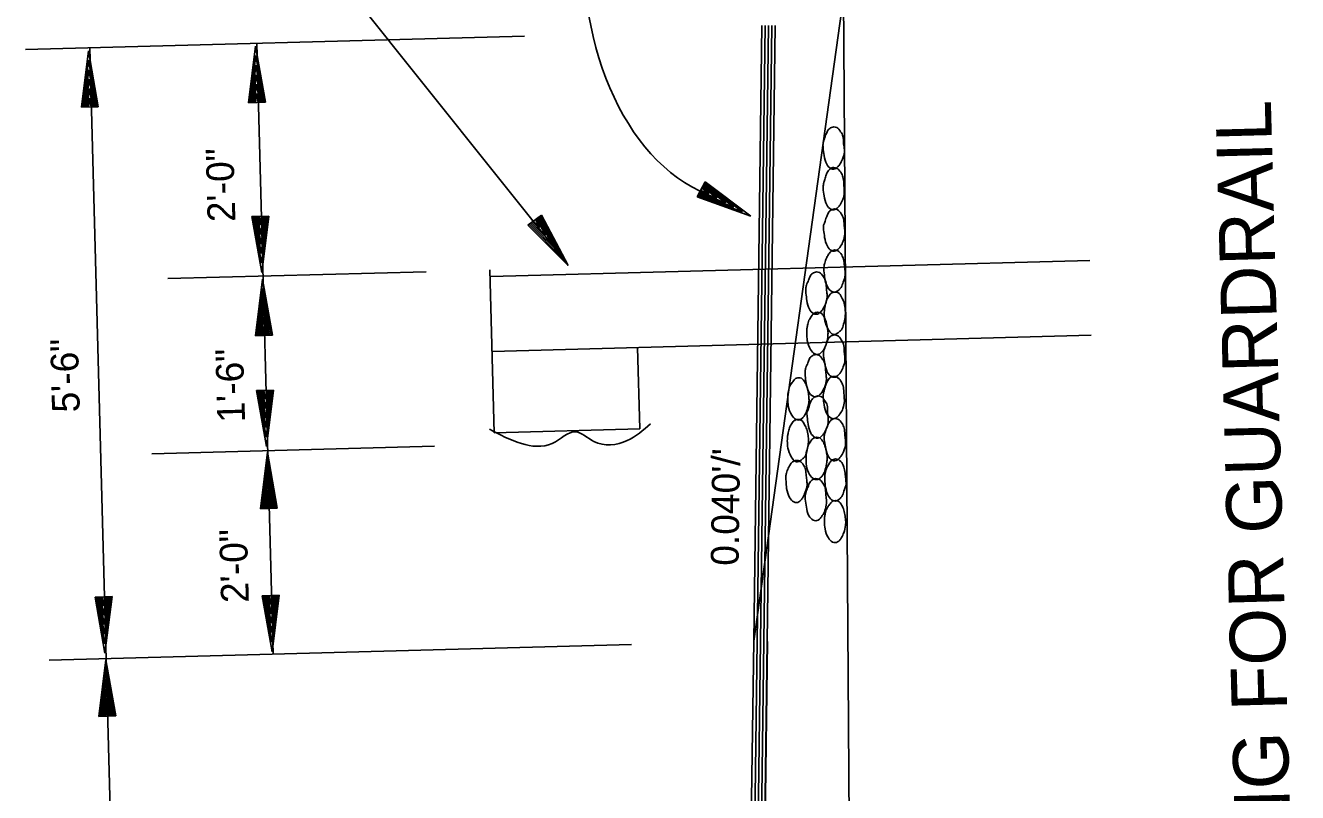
# Model space of a CAD drawing. Extents: x 1929624 to 1936506, y 596315 to 605721.
# Drawn here: x 1931754.9 to 1932029.9, y 600586 to 600751.8 of the extents above; entities that cross this region are included whole.
import ezdxf

# ---------------------------------------------------------------- set-up
doc = ezdxf.new("R2010")
doc.units = 0
doc.layers.add('Default', color=7, linetype='Continuous')

msp = doc.modelspace()

# ---------------------------------------------------------------- linework, layer by layer
at = {"layer": 'Default'}
for p, q in [((1931912.31, 600618.68), (1931945.12, 600854.29)), ((1931934.09, 600420.4), (1931931.39, 600809)), ((1931872.05, 600700.18), (1931818.5, 600767.22)), ((1931912.31, 600618.68), (1931914.06, 600751.77)), ((1931913.04, 600618.66), (1931914.79, 600751.75)), ((1931913.77, 600618.66), (1931915.52, 600751.74)), ((1931914.5, 600618.64), (1931916.25, 600751.73)), ((1931915.23, 600618.64), (1931916.98, 600751.73)), ((1931862.75, 600749.44), (1931754.9, 600746.55)), ((1931766.98, 600734.09), (1931768.5, 600746.31)), ((1931770.65, 600734.19), (1931768.5, 600746.31)), ((1931777.56, 600420.59), (1931768.8, 600746.92)), ((1931803.1, 600735.06), (1931804.62, 600747.28)), ((1931806.77, 600735.16), (1931804.62, 600747.28)), ((1931808.44, 600615.89), (1931804.9, 600747.89)), ((1931767.3, 600734.1), (1931768.55, 600744.27)), ((1931770.33, 600734.18), (1931768.55, 600744.27)), ((1931803.42, 600735.07), (1931804.68, 600745.24)), ((1931806.45, 600735.15), (1931804.68, 600745.24)), ((1931767.61, 600734.1), (1931768.61, 600742.18)), ((1931770.02, 600734.17), (1931768.61, 600742.18)), ((1931803.73, 600735.07), (1931804.73, 600743.15)), ((1931804.02, 600735.08), (1931804.79, 600741.11)), ((1931806.14, 600735.14), (1931804.73, 600743.15)), ((1931805.85, 600735.13), (1931804.79, 600741.11)), ((1931767.9, 600734.11), (1931768.67, 600740.14)), ((1931768.22, 600734.12), (1931768.72, 600738.1)), ((1931769.73, 600734.16), (1931768.67, 600740.14)), ((1931769.41, 600734.15), (1931768.72, 600738.1)), ((1931804.34, 600735.09), (1931804.84, 600739.07)), ((1931805.53, 600735.12), (1931804.84, 600739.07)), ((1931768.53, 600734.13), (1931768.77, 600736.06)), ((1931769.09, 600734.14), (1931768.77, 600736.06)), ((1931803.1, 600735.06), (1931806.77, 600735.16)), ((1931804.66, 600735.1), (1931804.9, 600737.03)), ((1931805.21, 600735.11), (1931804.9, 600737.03)), ((1931766.98, 600734.09), (1931770.65, 600734.19)), ((1931901.84, 600717.94), (1931900.08, 600714.74)), ((1931900.68, 600715.82), (1931904.44, 600714.44)), ((1931900.84, 600716.12), (1931902.66, 600715.44)), ((1931901.1, 600716.59), (1931902.66, 600715.44)), ((1931901.26, 600716.86), (1931904.44, 600714.44)), ((1931901.4, 600717.13), (1931906.26, 600713.44)), ((1931901.56, 600717.38), (1931908.02, 600712.5)), ((1931901.68, 600717.7), (1931909.87, 600711.5)), ((1931901.84, 600717.94), (1931911.67, 600710.53)), ((1931900.08, 600714.74), (1931911.67, 600710.53)), ((1931900.27, 600714.99), (1931909.87, 600711.5)), ((1931900.41, 600715.28), (1931908.02, 600712.5)), ((1931900.54, 600715.53), (1931906.26, 600713.44)), ((1931807.5, 600710.57), (1931803.83, 600710.48)), ((1931803.83, 600710.48), (1931805.98, 600698.36)), ((1931804.15, 600710.48), (1931805.93, 600700.4)), ((1931804.47, 600710.49), (1931805.87, 600702.48)), ((1931804.76, 600710.5), (1931805.82, 600704.53)), ((1931805.07, 600710.51), (1931805.76, 600706.57)), ((1931805.39, 600710.52), (1931805.71, 600708.61)), ((1931805.95, 600710.53), (1931805.71, 600708.61)), ((1931806.26, 600710.54), (1931805.76, 600706.57)), ((1931806.58, 600710.55), (1931805.82, 600704.53)), ((1931806.87, 600710.56), (1931805.87, 600702.48)), ((1931807.19, 600710.57), (1931805.93, 600700.4)), ((1931807.5, 600710.57), (1931805.98, 600698.36)), ((1931866.42, 600710.73), (1931863.51, 600708.59)), ((1931865.94, 600710.35), (1931869.71, 600703.23)), ((1931866.2, 600710.58), (1931871.01, 600701.49)), ((1931866.42, 600710.73), (1931872.2, 600699.87)), ((1931863.51, 600708.59), (1931872.2, 600699.87)), ((1931863.74, 600708.79), (1931871.01, 600701.49)), ((1931864.03, 600708.99), (1931869.71, 600703.23)), ((1931864.28, 600709.12), (1931868.52, 600704.85)), ((1931864.48, 600709.31), (1931867.31, 600706.47)), ((1931864.75, 600709.49), (1931866.1, 600708.12)), ((1931865.15, 600709.85), (1931866.1, 600708.12)), ((1931865.42, 600709.97), (1931867.31, 600706.47)), ((1931865.68, 600710.18), (1931868.52, 600704.85)), ((1931855.47, 600697.52), (1931984.97, 600701)), ((1931841.49, 600698.55), (1931785.65, 600697.06)), ((1931804.65, 600684.71), (1931806.17, 600696.93)), ((1931808.32, 600684.8), (1931806.17, 600696.93)), ((1931856.23, 600663.73), (1931855.29, 600698.93)), ((1931804.96, 600684.71), (1931806.22, 600694.89)), ((1931808, 600684.8), (1931806.22, 600694.89)), ((1931805.28, 600684.72), (1931806.28, 600692.8)), ((1931807.68, 600684.79), (1931806.28, 600692.8)), ((1931805.57, 600684.73), (1931806.33, 600690.76)), ((1931805.89, 600684.74), (1931806.39, 600688.72)), ((1931807.39, 600684.78), (1931806.33, 600690.76)), ((1931807.08, 600684.77), (1931806.39, 600688.72)), ((1931806.2, 600684.75), (1931806.44, 600686.68)), ((1931806.76, 600684.76), (1931806.44, 600686.68)), ((1931804.65, 600684.71), (1931808.32, 600684.8)), ((1931855.76, 600681.34), (1931985.28, 600684.82)), ((1931887.67, 600664.57), (1931887.19, 600682.18)), ((1931808.54, 600672.97), (1931804.87, 600672.87)), ((1931804.87, 600672.87), (1931807.02, 600660.75)), ((1931805.18, 600672.88), (1931806.96, 600662.79)), ((1931805.5, 600672.89), (1931806.91, 600664.88)), ((1931805.79, 600672.9), (1931806.85, 600666.92)), ((1931806.11, 600672.91), (1931806.8, 600668.96)), ((1931806.42, 600672.92), (1931806.74, 600671)), ((1931806.98, 600672.93), (1931806.74, 600671)), ((1931807.3, 600672.94), (1931806.8, 600668.96)), ((1931807.61, 600672.95), (1931806.85, 600666.92)), ((1931807.9, 600672.96), (1931806.91, 600664.88)), ((1931808.22, 600672.96), (1931806.96, 600662.79)), ((1931808.54, 600672.97), (1931807.02, 600660.75)), ((1931856.23, 600663.73), (1931887.67, 600664.57)), ((1931843.3, 600660.85), (1931782.21, 600659.21)), ((1931805.68, 600647.32), (1931807.19, 600659.54)), ((1931809.34, 600647.42), (1931807.19, 600659.54)), ((1931805.99, 600647.33), (1931807.25, 600657.5)), ((1931806.31, 600647.34), (1931807.31, 600655.41)), ((1931809.03, 600647.41), (1931807.25, 600657.5)), ((1931808.71, 600647.4), (1931807.31, 600655.41)), ((1931806.6, 600647.35), (1931807.36, 600653.37)), ((1931808.42, 600647.4), (1931807.36, 600653.37)), ((1931806.91, 600647.36), (1931807.42, 600651.33)), ((1931808.1, 600647.39), (1931807.42, 600651.33)), ((1931805.68, 600647.32), (1931809.34, 600647.42)), ((1931807.23, 600647.36), (1931807.47, 600649.29)), ((1931807.79, 600647.38), (1931807.47, 600649.29)), ((1931773.61, 600628.33), (1931769.94, 600628.23)), ((1931769.94, 600628.23), (1931772.09, 600616.11)), ((1931770.26, 600628.24), (1931772.04, 600618.15)), ((1931770.58, 600628.25), (1931771.98, 600620.24)), ((1931770.87, 600628.25), (1931771.93, 600622.28)), ((1931771.18, 600628.26), (1931771.87, 600624.32)), ((1931771.5, 600628.27), (1931771.82, 600626.36)), ((1931772.06, 600628.29), (1931771.82, 600626.36)), ((1931772.37, 600628.29), (1931771.87, 600624.32)), ((1931772.69, 600628.3), (1931771.93, 600622.28)), ((1931772.98, 600628.31), (1931771.98, 600620.24)), ((1931773.3, 600628.32), (1931772.04, 600618.15)), ((1931773.61, 600628.33), (1931772.09, 600616.11)), ((1931809.73, 600628.64), (1931806.06, 600628.54)), ((1931806.06, 600628.54), (1931808.21, 600616.42)), ((1931806.37, 600628.55), (1931808.15, 600618.46)), ((1931806.69, 600628.56), (1931808.1, 600620.55)), ((1931806.98, 600628.57), (1931808.04, 600622.59)), ((1931807.3, 600628.58), (1931807.99, 600624.63)), ((1931807.61, 600628.58), (1931807.93, 600626.67)), ((1931808.17, 600628.6), (1931807.93, 600626.67)), ((1931808.49, 600628.61), (1931807.99, 600624.63)), ((1931808.8, 600628.62), (1931808.04, 600622.59)), ((1931809.09, 600628.62), (1931808.1, 600620.55)), ((1931809.41, 600628.63), (1931808.15, 600618.46)), ((1931809.73, 600628.64), (1931808.21, 600616.42)), ((1931885.93, 600617.97), (1931760, 600614.59)), ((1931912.31, 600618.68), (1931910.39, 600472.78)), ((1931913.04, 600618.7), (1931911.12, 600472.8)), ((1931913.77, 600618.67), (1931911.85, 600472.77)), ((1931914.5, 600618.69), (1931912.58, 600472.79)), ((1931915.23, 600618.66), (1931913.31, 600472.76)), ((1931915.32, 600618.66), (1931913.4, 600472.86)), ((1931770.73, 600602.46), (1931772.25, 600614.68)), ((1931774.4, 600602.56), (1931772.25, 600614.68)), ((1931771.05, 600602.47), (1931772.31, 600612.64)), ((1931774.08, 600602.55), (1931772.31, 600612.64)), ((1931771.36, 600602.48), (1931772.36, 600610.55)), ((1931773.77, 600602.54), (1931772.36, 600610.55)), ((1931771.66, 600602.48), (1931772.42, 600608.51)), ((1931771.97, 600602.49), (1931772.47, 600606.47)), ((1931773.48, 600602.53), (1931772.42, 600608.51)), ((1931773.16, 600602.52), (1931772.47, 600606.47)), ((1931772.29, 600602.5), (1931772.53, 600604.43)), ((1931772.85, 600602.52), (1931772.53, 600604.43)), ((1931770.73, 600602.46), (1931774.4, 600602.56))]:
    msp.add_line(p, q, dxfattribs=at)
msp.add_ellipse((1931915.32, 600773.75), major_axis=(-5.72, -60.23), ratio=0.655798, start_param=4.712389, end_param=6.093533, dxfattribs=at)
for points in [[(1931927.31, 600725.35), (1931927.55, 600723.65), (1931928.09, 600721.77), (1931929.04, 600720.82), (1931929.58, 600720.69), (1931930.53, 600721.25), (1931930.96, 600721.8), (1931931.51, 600722.88), (1931931.91, 600724.45), (1931931.89, 600725.23), (1931931.71, 600726.44), (1931931.62, 600727.8), (1931931.11, 600728.8), (1931930.26, 600729.7), (1931929.62, 600729.83), (1931928.76, 600729.52), (1931928.19, 600728.77), (1931927.87, 600728.03), (1931927.51, 600727), (1931927.33, 600726.32), (1931927.31, 600725.35)], [(1931927.3, 600716.57), (1931927.54, 600714.92), (1931928.12, 600712.99), (1931929.02, 600712.05), (1931929.61, 600711.92), (1931930.57, 600712.48), (1931930.99, 600713.02), (1931931.59, 600714.16), (1931931.89, 600715.67), (1931931.87, 600716.45), (1931931.79, 600717.66), (1931931.61, 600719.02), (1931931.14, 600720.03), (1931930.24, 600720.93), (1931929.66, 600721.06), (1931928.79, 600720.74), (1931928.23, 600720), (1931927.91, 600719.26), (1931927.59, 600718.23), (1931927.42, 600717.59), (1931927.3, 600716.57)], [(1931927.42, 600707.57), (1931927.65, 600705.97), (1931928.24, 600704.04), (1931929.14, 600703.1), (1931929.73, 600702.97), (1931930.69, 600703.53), (1931931.11, 600704.07), (1931931.66, 600705.16), (1931932.01, 600706.67), (1931931.99, 600707.5), (1931931.86, 600708.71), (1931931.73, 600710.02), (1931931.26, 600711.03), (1931930.36, 600711.98), (1931929.77, 600712.11), (1931928.91, 600711.79), (1931928.34, 600711.05), (1931928.02, 600710.31), (1931927.66, 600709.23), (1931927.44, 600708.59), (1931927.42, 600707.57)], [(1931927.51, 600698.7), (1931927.7, 600697.1), (1931928.33, 600695.17), (1931929.23, 600694.27), (1931929.82, 600694.14), (1931930.78, 600694.66), (1931931.2, 600695.15), (1931931.66, 600696.28), (1931932.1, 600697.8), (1931932.08, 600698.63), (1931931.95, 600699.84), (1931931.72, 600701.2), (1931931.35, 600702.16), (1931930.45, 600703.11), (1931929.87, 600703.24), (1931929, 600702.92), (1931928.44, 600702.18), (1931928.02, 600701.44), (1931927.66, 600700.41), (1931927.53, 600699.72), (1931927.51, 600698.7)], [(1931923.58, 600693.91), (1931923.82, 600692.31), (1931924.35, 600690.43), (1931925.3, 600689.48), (1931925.84, 600689.35), (1931926.85, 600689.92), (1931927.27, 600690.46), (1931927.82, 600691.55), (1931928.17, 600693.11), (1931928.15, 600693.89), (1931928.02, 600695.1), (1931927.89, 600696.41), (1931927.37, 600697.47), (1931926.52, 600698.37), (1931925.89, 600698.49), (1931925.02, 600698.18), (1931924.46, 600697.44), (1931924.18, 600696.7), (1931923.73, 600695.67), (1931923.6, 600694.93), (1931923.58, 600693.91)], [(1931927.57, 600689.56), (1931927.71, 600687.96), (1931928.44, 600686.08), (1931929.24, 600685.13), (1931929.78, 600685), (1931930.79, 600685.56), (1931931.31, 600686.02), (1931931.76, 600687.2), (1931932.07, 600688.66), (1931932.14, 600689.49), (1931932.06, 600690.7), (1931931.78, 600692.06), (1931931.32, 600693.02), (1931930.51, 600694.02), (1931929.88, 600694.15), (1931929.01, 600693.83), (1931928.4, 600693.08), (1931928.08, 600692.35), (1931927.77, 600691.27), (1931927.64, 600690.58), (1931927.57, 600689.56)], [(1931923.81, 600685.26), (1931923.9, 600683.65), (1931924.59, 600681.73), (1931925.53, 600680.78), (1931926.07, 600680.65), (1931927.08, 600681.21), (1931927.5, 600681.76), (1931927.96, 600682.84), (1931928.31, 600684.4), (1931928.38, 600685.23), (1931928.25, 600686.4), (1931927.97, 600687.7), (1931927.56, 600688.71), (1931926.76, 600689.66), (1931926.12, 600689.79), (1931925.25, 600689.48), (1931924.69, 600688.73), (1931924.27, 600688.04), (1931923.96, 600686.96), (1931923.83, 600686.28), (1931923.81, 600685.26)], [(1931927.44, 600680.39), (1931927.68, 600678.7), (1931928.22, 600676.87), (1931929.17, 600675.87), (1931929.71, 600675.74), (1931930.71, 600676.3), (1931931.13, 600676.85), (1931931.69, 600677.98), (1931932.04, 600679.5), (1931932.01, 600680.27), (1931931.88, 600681.49), (1931931.75, 600682.89), (1931931.24, 600683.85), (1931930.39, 600684.75), (1931929.75, 600684.88), (1931928.89, 600684.57), (1931928.32, 600683.82), (1931928.05, 600683.13), (1931927.69, 600682.05), (1931927.46, 600681.42), (1931927.44, 600680.39)], [(1931923.43, 600676.06), (1931923.66, 600674.46), (1931924.2, 600672.58), (1931925.15, 600671.63), (1931925.69, 600671.5), (1931926.69, 600672.06), (1931927.12, 600672.61), (1931927.67, 600673.69), (1931928.02, 600675.26), (1931928, 600676.03), (1931927.87, 600677.25), (1931927.73, 600678.55), (1931927.22, 600679.61), (1931926.37, 600680.51), (1931925.73, 600680.64), (1931924.87, 600680.33), (1931924.3, 600679.58), (1931924.03, 600678.84), (1931923.57, 600677.81), (1931923.45, 600677.08), (1931923.43, 600676.06)], [(1931919.7, 600671.1), (1931919.79, 600669.5), (1931920.53, 600667.58), (1931921.43, 600666.63), (1931922.01, 600666.5), (1931922.97, 600667.06), (1931923.39, 600667.6), (1931923.85, 600668.69), (1931924.25, 600670.25), (1931924.27, 600671.08), (1931924.14, 600672.24), (1931923.87, 600673.55), (1931923.45, 600674.56), (1931922.65, 600675.51), (1931922.06, 600675.64), (1931921.19, 600675.32), (1931920.63, 600674.58), (1931920.16, 600673.89), (1931919.85, 600672.81), (1931919.72, 600672.12), (1931919.7, 600671.1)], [(1931927.32, 600671.43), (1931927.56, 600669.78), (1931928.14, 600667.85), (1931929.04, 600666.91), (1931929.63, 600666.78), (1931930.59, 600667.34), (1931931.01, 600667.88), (1931931.61, 600669.02), (1931931.91, 600670.53), (1931931.89, 600671.31), (1931931.81, 600672.52), (1931931.63, 600673.88), (1931931.16, 600674.89), (1931930.26, 600675.79), (1931929.68, 600675.92), (1931928.81, 600675.6), (1931928.25, 600674.86), (1931927.93, 600674.12), (1931927.61, 600673.09), (1931927.44, 600672.45), (1931927.32, 600671.43)], [(1931923.89, 600667.22), (1931924.08, 600665.62), (1931924.66, 600663.69), (1931925.62, 600662.7), (1931926.15, 600662.57), (1931927.11, 600663.13), (1931927.53, 600663.67), (1931928.14, 600664.81), (1931928.43, 600666.32), (1931928.41, 600667.15), (1931928.28, 600668.31), (1931928.2, 600669.72), (1931927.69, 600670.68), (1931926.84, 600671.58), (1931926.2, 600671.71), (1931925.33, 600671.39), (1931924.77, 600670.7), (1931924.45, 600669.96), (1931924.14, 600668.93), (1931923.86, 600668.24), (1931923.89, 600667.22)], [(1931919.58, 600662.03), (1931919.72, 600660.43), (1931920.45, 600658.56), (1931921.25, 600657.6), (1931921.79, 600657.47), (1931922.8, 600658.04), (1931923.32, 600658.49), (1931923.78, 600659.67), (1931924.08, 600661.13), (1931924.15, 600661.96), (1931924.07, 600663.17), (1931923.79, 600664.53), (1931923.33, 600665.49), (1931922.52, 600666.49), (1931921.89, 600666.62), (1931921.02, 600666.3), (1931920.41, 600665.56), (1931920.09, 600664.82), (1931919.78, 600663.74), (1931919.65, 600663.06), (1931919.58, 600662.03)], [(1931927.57, 600662.29), (1931927.81, 600660.69), (1931928.39, 600658.76), (1931929.3, 600657.81), (1931929.88, 600657.68), (1931930.84, 600658.24), (1931931.26, 600658.79), (1931931.82, 600659.87), (1931932.17, 600661.39), (1931932.14, 600662.22), (1931932.01, 600663.43), (1931931.88, 600664.74), (1931931.42, 600665.75), (1931930.52, 600666.69), (1931929.93, 600666.82), (1931929.06, 600666.51), (1931928.5, 600665.76), (1931928.18, 600665.03), (1931927.82, 600663.95), (1931927.59, 600663.31), (1931927.57, 600662.29)], [(1931855.19, 600664.55), (1931862.11, 600661.43), (1931868.77, 600661.44), (1931873.83, 600663.96), (1931877.77, 600661.85), (1931884.94, 600662.04), (1931890.02, 600665.68)], [(1931923.64, 600658.23), (1931923.73, 600656.63), (1931924.41, 600654.7), (1931925.36, 600653.75), (1931925.9, 600653.62), (1931926.91, 600654.18), (1931927.33, 600654.73), (1931927.79, 600655.81), (1931928.13, 600657.38), (1931928.21, 600658.2), (1931928.08, 600659.37), (1931927.8, 600660.67), (1931927.38, 600661.68), (1931926.58, 600662.63), (1931925.95, 600662.76), (1931925.08, 600662.45), (1931924.52, 600661.7), (1931924.1, 600661.01), (1931923.79, 600659.93), (1931923.66, 600659.25), (1931923.64, 600658.23)], [(1931927.68, 600653.55), (1931927.86, 600651.95), (1931928.5, 600650.02), (1931929.4, 600649.12), (1931929.99, 600648.99), (1931930.94, 600649.5), (1931931.37, 600650), (1931931.82, 600651.13), (1931932.27, 600652.65), (1931932.25, 600653.48), (1931932.12, 600654.69), (1931931.89, 600656.04), (1931931.52, 600657.01), (1931930.62, 600657.95), (1931930.03, 600658.08), (1931929.17, 600657.77), (1931928.6, 600657.02), (1931928.19, 600656.28), (1931927.82, 600655.25), (1931927.7, 600654.57), (1931927.68, 600653.55)], [(1931919.3, 600653.31), (1931919.44, 600651.71), (1931920.07, 600649.79), (1931921.02, 600648.79), (1931921.56, 600648.66), (1931922.52, 600649.17), (1931922.94, 600649.77), (1931923.44, 600650.9), (1931923.84, 600652.46), (1931923.82, 600653.29), (1931923.69, 600654.45), (1931923.51, 600655.76), (1931923.09, 600656.77), (1931922.24, 600657.62), (1931921.61, 600657.75), (1931920.74, 600657.44), (1931920.17, 600656.79), (1931919.8, 600656.1), (1931919.4, 600655.02), (1931919.27, 600654.33), (1931919.3, 600653.31)], [(1931923.46, 600649.4), (1931923.7, 600647.7), (1931924.24, 600645.82), (1931925.19, 600644.88), (1931925.72, 600644.74), (1931926.73, 600645.26), (1931927.15, 600645.85), (1931927.71, 600646.94), (1931928.05, 600648.5), (1931928.03, 600649.28), (1931927.9, 600650.49), (1931927.77, 600651.85), (1931927.26, 600652.86), (1931926.41, 600653.71), (1931925.77, 600653.84), (1931924.91, 600653.52), (1931924.34, 600652.78), (1931924.07, 600652.09), (1931923.66, 600651.01), (1931923.48, 600650.37), (1931923.46, 600649.4)], [(1931927.63, 600644.55), (1931927.73, 600642.95), (1931928.46, 600641.03), (1931929.36, 600640.13), (1931929.94, 600640), (1931930.9, 600640.51), (1931931.32, 600641.1), (1931931.78, 600642.14), (1931932.18, 600643.75), (1931932.2, 600644.53), (1931932.07, 600645.74), (1931931.8, 600647.05), (1931931.38, 600648.06), (1931930.58, 600648.96), (1931929.99, 600649.09), (1931929.12, 600648.77), (1931928.56, 600648.03), (1931928.09, 600647.34), (1931927.78, 600646.26), (1931927.65, 600645.57), (1931927.63, 600644.55)]]:
    msp.add_spline(points, degree=3, dxfattribs=at)

# ---------------------------------------------------------------- texts
for s, height, rotation, p in [('WIDENING FOR GUARDRAIL', 12, 91.5377, (1932029.97, 600517.34)), ('2\'-0"', 6, 91.5377, (1931800.29, 600709.36)), ('5\'-6"', 6, 91.5377, (1931766.66, 600668.2)), ('1\'-6"', 6, 91.5377, (1931802.38, 600666.03)), ("0.040'/'", 6, 89.2471, (1931909.04, 600634.98)), ('2\'-0"', 6, 91.5377, (1931803.2, 600627.06))]:
    msp.add_text(s, height=height, rotation=rotation, dxfattribs=at).set_placement(p)

doc.saveas('drawing.dxf')
